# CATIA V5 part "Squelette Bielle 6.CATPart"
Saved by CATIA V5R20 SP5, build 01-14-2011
Part number: Squelette Bielle 6
Bounding box of the stored display mesh (mm): x -270 to -250, y -200 to 100, z -10 to 50
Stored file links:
  U:\CFAO\Thinkmotion\Squelette Bielle 6.CATPart
  U:\CFAO\Thinkmotion\Bras Articule.CATProduct
  U:\CFAO\Thinkmotion\Squelette general.CATPart
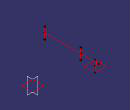
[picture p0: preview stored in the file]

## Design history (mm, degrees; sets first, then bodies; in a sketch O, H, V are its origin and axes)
Set1
  Line1: type PtPt, FirstPoint Point1, SecondPoint Point2
  Line2: type PtPt, FirstPoint Point2, SecondPoint Point3
  Line3: type PtPt, FirstPoint Point3, SecondPoint Point4
  Line4: type Normal, RefPoint Point1, RefSkin Plane2, Start -30, End 30
  Line5: type Normal, RefPoint Point3, RefSkin Plane2, Start -30, End 30
  Line6: type Normal, RefPoint Point4, RefSkin Plane2, Start -30, End 30
  Plane1: type OffsetPt, RefPlane xy-plane, RefPoint Point1
Set2
  Point1 to Point4: linked copy from another document
  Plane2: linked copy from another document
Body1 (main body)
